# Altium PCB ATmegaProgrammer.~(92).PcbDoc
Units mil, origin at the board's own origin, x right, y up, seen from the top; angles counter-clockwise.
Board outline 2130 x 2720 mil, 2 copper layers (Top Layer, Bottom Layer); 14 components, 9 nets, 76 pads, 4 vias.
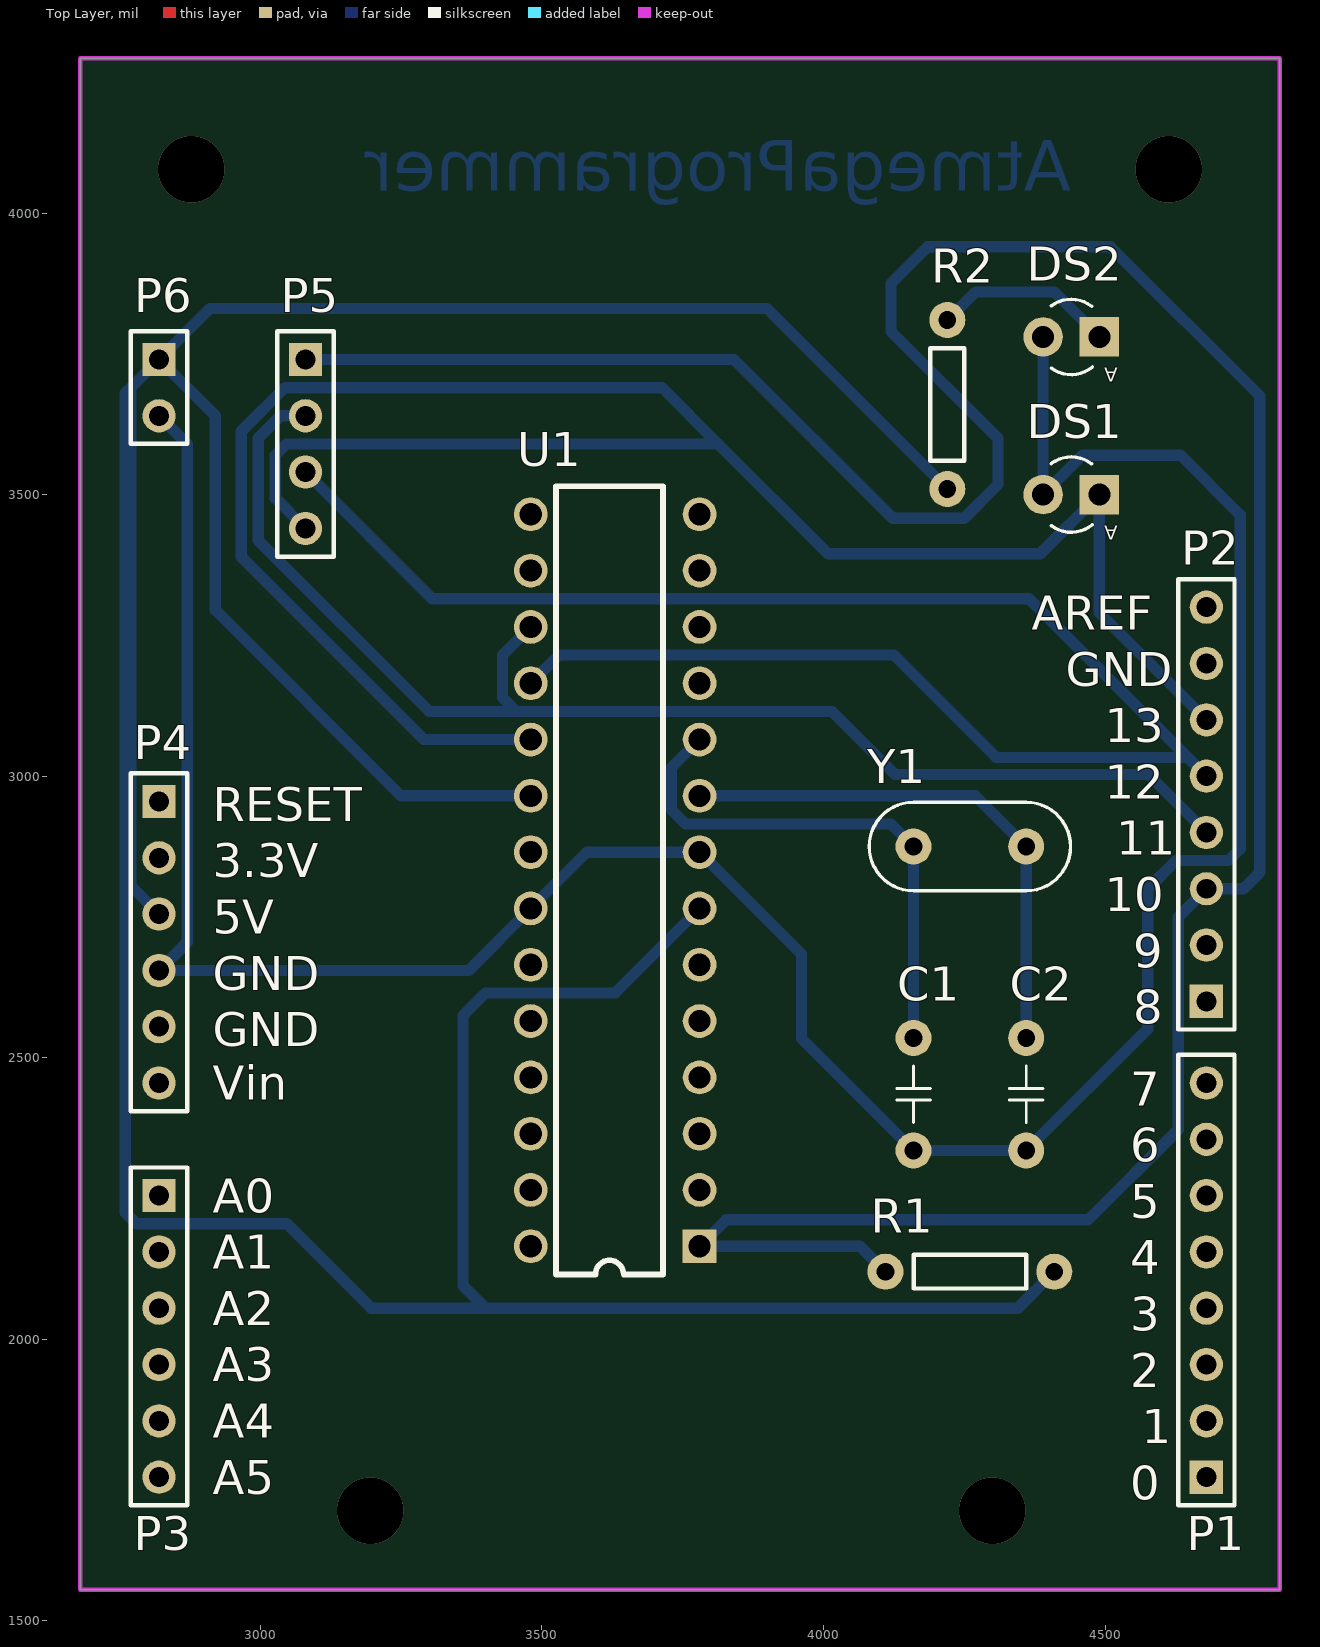
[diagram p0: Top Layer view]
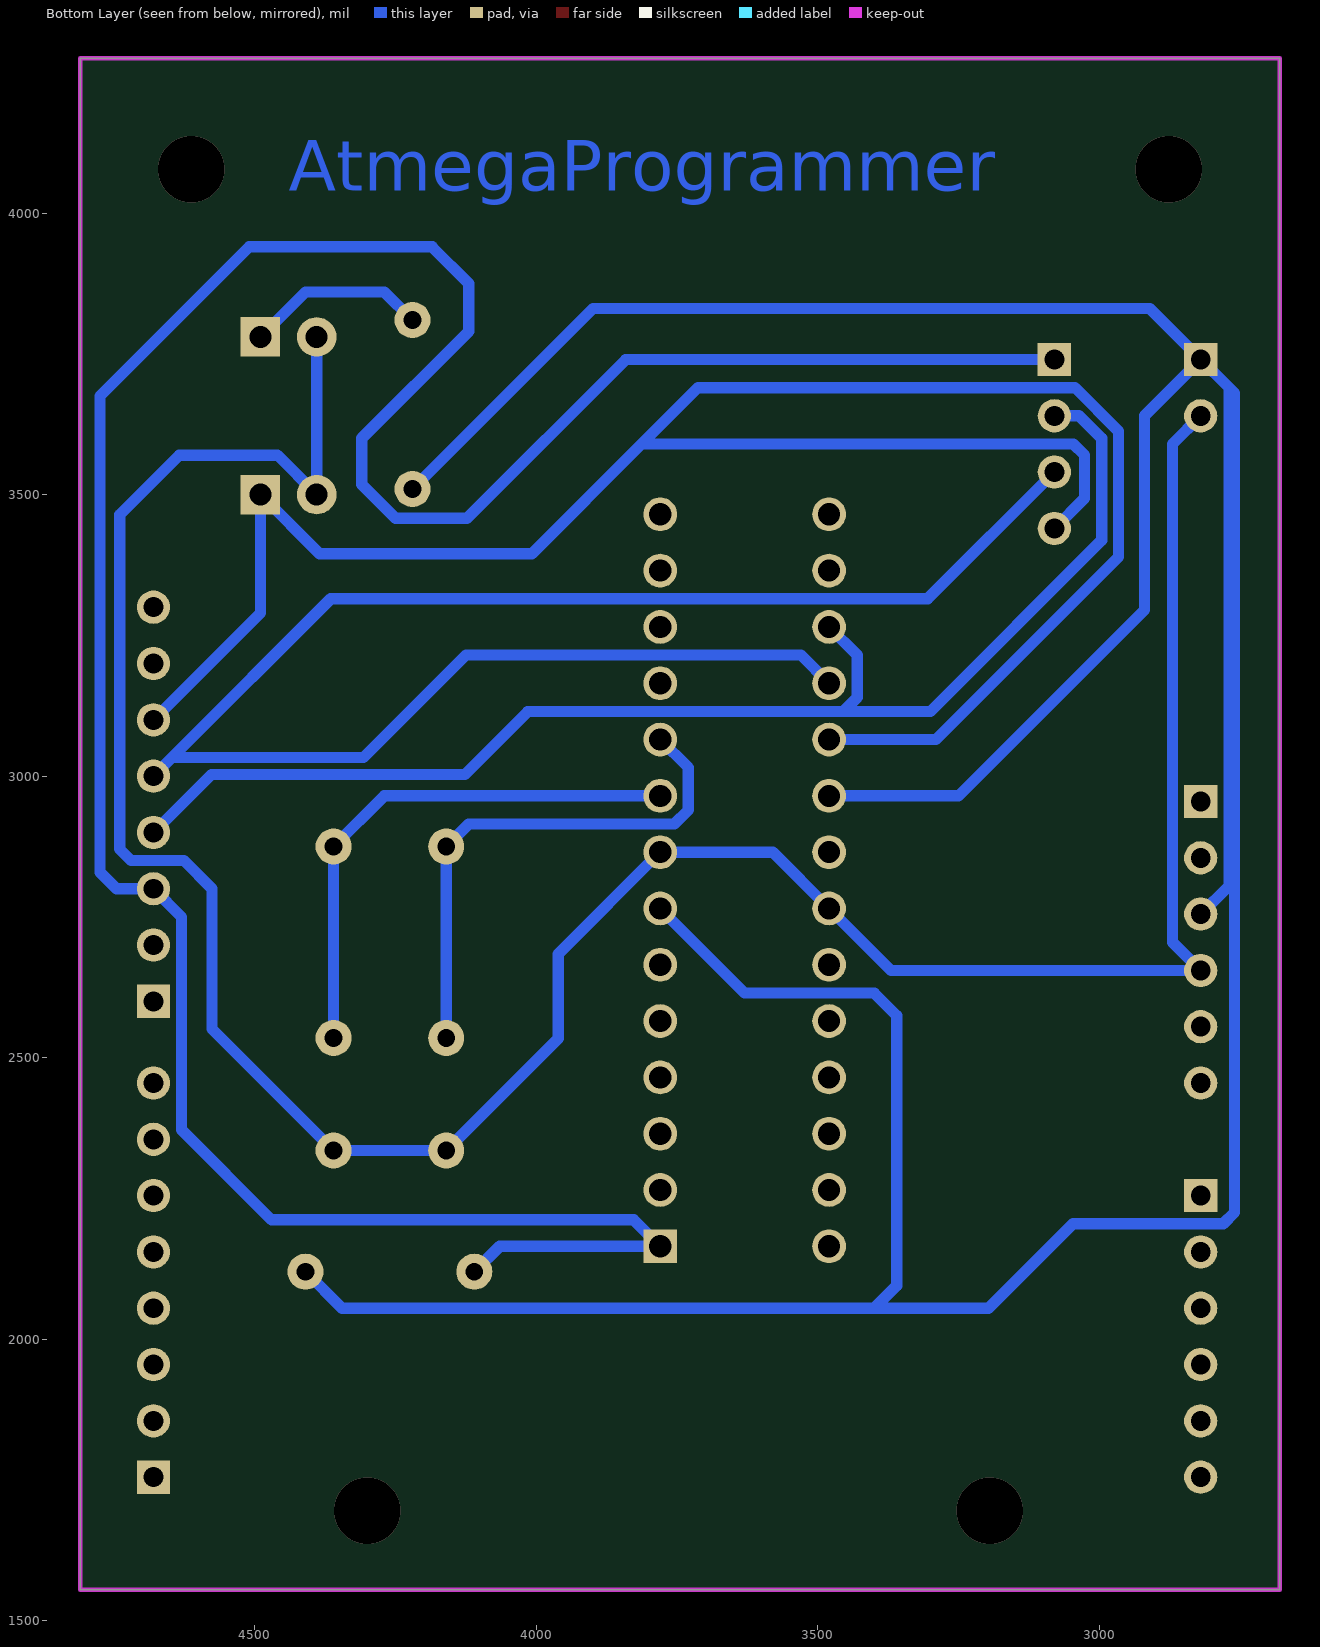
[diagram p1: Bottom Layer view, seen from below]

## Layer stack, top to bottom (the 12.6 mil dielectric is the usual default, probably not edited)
Top Layer: signal copper 1.4
Dielectric: dielectric 12.6, FR-4, Dk 4.8
Bottom Layer: signal copper 1.4

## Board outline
2680,1555 4810,1555 4810,4275 2680,4275

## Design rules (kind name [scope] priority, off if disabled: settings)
Clearance [All] p1: gap=10
PolygonConnect [All] p1: connectstyle=Relief reliefconductorwidth=10 reliefentries=4 polygonreliefangle="90 Angle"
RoutingLayers [All] p1: top layer_v5=FALSE bottom layer_v5=TRUE
RoutingVias [All] p1: holewidth=28 width=50 viastyle="Through Hole" minholewidth=28 minwidth=50 maxholewidth=28 maxwidth=50
SilkscreenOverComponentPads [All] p1: minsilkscreentomaskgap=10
SolderMaskExpansion [All] p1: expansion=4
Width [All] p1: maxlimit=40 minlimit=10 preferedwidth=20
26 further rules are at their usual default settings.

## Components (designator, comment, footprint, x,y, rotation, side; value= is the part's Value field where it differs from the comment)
C1 "20pF" C200 4160,2435 r180 top
C2 "20pF" C200 4360,2435 r180 top
DS1 "LED" LED-3mm_G 4440,3500 r180 top
DS2 "LED" LED-3mm_G 4440,3780 r180 top
P1 "Header 8" HDR1X8 4680,1755 r90 top
P2 "Header 8" HDR1X8 4680,2600 r90 top
P3 "Header 6" HDR1X6 2820,2255 r270 top
P4 "Header 6" HDR1X6 2820,2955 r270 top
P5 "Header 4" HDR1X4 3080,3740 r270 top
P6 "Header 2" HDR1X2 2820,3740 r270 top
R1 "10k" AXIAL-0.3 4260,2120 r0 top
R2 "220" AXIAL-0.3 4220,3660 r270 top
U1 "ATmega328" DIP28 3620,2820 r180 top
Y1 "16MHz" XTAL4-8 4260,2875 r180 top

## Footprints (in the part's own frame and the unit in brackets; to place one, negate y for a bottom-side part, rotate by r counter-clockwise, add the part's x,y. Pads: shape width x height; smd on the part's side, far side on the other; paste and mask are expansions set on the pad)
AXIAL-0.3 [mil] "0.3\" Resistor; 2 Leads"
  round 64 hole 31.5: 1(-150,0) 2(150,0)
  silkscreen extent -100,-30 100,30, body extent -161,-39 165,39, height 86
C200 [mil] "鹅溅筿甧竟"
  round 64 hole 31.5: 1(0,100) 2(0,-100)
  silkscreen extent -30,-50 30,50, body extent -41,-136 39,135, height 354
DIP28 [mil]
  rect 60x60 hole 39.37: 1(-160,655)
  round 60 hole 39.37: 2(-160,555) 3(-160,455) 4(-160,355) 5(-160,255) 6(-160,155) 7(-160,55) 8(-160,-45) 9(-160,-145) 10(-160,-245) 11(-160,-345) 12(-160,-445) 13(-160,-545) 14(-160,-645) 15(140,-645) 16(140,-545) 17(140,-445) 18(140,-345) 19(140,-245) 20(140,-145) 21(140,-45) 22(140,55) 23(140,155) 24(140,255) 25(140,355) 26(140,455) 27(140,555) 28(140,655)
  silkscreen extent -95,-695 95,705, body extent -95,-695 95,705, height 130
HDR1X2 [mm] "Connector; Header; 2 Position"
  rect 1.5x1.5 hole 0.9: 1(0,0)
  round 1.5 hole 0.9: 2(2.54,0)
  silkscreen extent -1.27,-1.27 3.81,1.27
HDR1X4 [mm] "Connector; Header; 4 Position"
  rect 1.5x1.5 hole 0.9: 1(0,0)
  round 1.5 hole 0.9: 2(2.54,0) 3(5.08,0) 4(7.62,0)
  silkscreen extent -1.27,-1.27 8.89,1.27
HDR1X6 [mm] "Connector; Header; 6 Position"
  rect 1.5x1.5 hole 0.9: 1(0,0)
  round 1.5 hole 0.9: 2(2.54,0) 3(5.08,0) 4(7.62,0) 5(10.16,0) 6(12.7,0)
  silkscreen extent -1.27,-1.27 13.97,1.27
HDR1X8 [mm] "Connector; Header; 8 Position"
  rect 1.5x1.5 hole 0.9: 1(0,0)
  round 1.5 hole 0.9: 2(2.54,0) 3(5.08,0) 4(7.62,0) 5(10.16,0) 6(12.7,0) 7(15.24,0) 8(17.78,0)
  silkscreen extent -1.27,-1.27 19.05,1.27
LED-3mm_G [mil] "3mm LED_Green"
  rect 70x70 hole 39: 1(-50,0)
  round 70 hole 39: 2(50,0)
  silkscreen extent -38,-67 35,67, body extent -66,-68 67,66, height 181
XTAL4-8 [mil]
  round 64 hole 31.5: 1(-100,0) 2(100,0)
  silkscreen extent -179,-79 179,79, body extent -178,-80 192,79, height 157

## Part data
C1 C2: library part Cap, "Capacitor"
DS1 DS2: "Typical INFRARED GaAs LED"
P1 P2: "Header, 8-Pin"
P3 P4: "Header, 6-Pin"
P5: "Header, 4-Pin"
P6: "Header, 2-Pin"
R1 R2: library part Res, "Resistor"
U1: "ATmega¨t¦C³æ´¹¤ù"
Y1: library part XTAL, "Crystal Oscillator"

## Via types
v1: diameter 118.11, hole 118.11, Top Layer to Bottom Layer, 4 vias

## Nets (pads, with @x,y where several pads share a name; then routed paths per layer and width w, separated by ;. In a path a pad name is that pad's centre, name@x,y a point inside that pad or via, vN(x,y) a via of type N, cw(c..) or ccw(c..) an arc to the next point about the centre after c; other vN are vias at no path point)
GND: C1.1 C2.1 DS1.2 DS2.2 P4.4 P6.2 U1.8 U1.22 | length 5004.9
  Bottom Layer w20: P6.2 2870,3590 2870,2705 P4.4 3370,2655 U1.22 3580,2865 U1.8 3961,2684 3961,2534 C1.1 C2.1 4576,2551 4576,2800 4626,2850 4719.53,2850 4740,2870.47 4740,3464 4634,3570 4460,3570 DS1.2 DS2.2
MISO: P2.5 P5.3 U1.18 | length 3133.4
  Bottom Layer w20: P5.3 3305,3315 4365,3315 4647,3033 ; U1.18 3530,3215 4125,3215 4307,3033 4647,3033 ; 4647,3033 P2.5 4647,3033
MOSI: P2.4 P5.2 U1.17 | length 2921.6
  Bottom Layer w20: P5.2 3036,3640 2996,3600 2996,3419 3300,3115 3455,3115 ; U1.17 3430,3215 3430,3140 3455,3115 ; P2.4 4577,3003 4127,3003 4015,3115 ; 3455,3115 4015,3115 ; 3455,3115 4015,3115
NetC1_2: C1.2 U1.10 Y1.2 | length 942.6
  Bottom Layer w20: U1.10 3730,3015 3730,2940 3755,2915 4120,2915 Y1.2 C1.2
NetC2_2: C2.2 U1.9 Y1.1 | length 957.3
  Bottom Layer w20: U1.9 4270,2965 Y1.1 C2.2
NetDS2_1: DS2.1 R2.1 | length 323.8
  Bottom Layer w20: R2.1 4270,3860 4410,3860 DS2.1
RESET: P2.3 P5.1 R1.1 U1.1 | length 5285
  Bottom Layer w20: P5.1 3841,3740 4123,3458 4250,3458 4310,3518 4310,3600 4120,3790 4120,3875 4185,3940 4510,3940 4775,3675 4775,2829.29 4745.71,2800 P2.3 4630,2750 4630,2372 4470,2212 3827,2212 U1.1 4065,2165 R1.1
SCK: DS1.1 P2.6 P5.4 U1.19 | length 4294.9
  Bottom Layer w20: P5.4 3026.45,3493.55 3026.45,3570 3046.45,3590 3813,3590 ; U1.19 3290,3065 2966,3389 2966,3612.43 3043.57,3690 3713,3690 3813,3590 ; P2.6 4490,3290 DS1.1 4385,3395 4008,3395 ; 3813,3590 4008,3395 ; 3813,3590 4008,3395
VCC: P4.3 P6.1 R1.2 R2.2 U1.7 U1.20 | length 9047.2
  Bottom Layer w20: P4.3 2770,2805 2770,3690 ; U1.20 3250,2965 2920,3295 2920,3640 P6.1 ; U1.7 3630,2615 3400,2615 3360,2575 3360,2095 3400,2055 ; R2.2 3899.49,3830.51 2910.51,3830.51 P6.1 ; R1.2 4345,2055 ; 2770,3690 P6.1 ; 2770,3690 2760,3680 2760,2225 2780,2205 3047,2205 3197,2055 3400,2055 ; 2770,3690 P6.1 ; 3400,2055 4345,2055 ; 3400,2055 4345,2055
pads on no net: P1.1 P1.2 P1.3 P1.4 P1.5 P1.6 P1.7 P1.8 P2.1 P2.2 P2.7 P2.8 P3.1 P3.2 P3.3 P3.4 P3.5 P3.6 P4.1 P4.2 P4.5 P4.6 U1.2 U1.3 U1.4 U1.5 U1.6 U1.11 U1.12 U1.13 U1.14 U1.15 U1.16 U1.21 U1.23 U1.24 U1.25 U1.26 U1.27 U1.28
copper on no net:
  other v1: 3195,1695 4300,1695 2876.85,4078.15 4613.15,4078.15

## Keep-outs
Keep-Out Layer:
  the board outline again, w7.87

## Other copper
Bottom Layer:
  text "AtmegaProgrammer" at 4440,4040 h90

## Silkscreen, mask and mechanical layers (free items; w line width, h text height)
Top Overlay:
  lines w7.87: 0,0 0,200 ; 20,0 35,0 ; 55,0 195,0 ; 2770,2246.75 2770,2255
  text "AREF" at 4370,3260 h60
  text "GND" at 4429.98,3160 h60
  text "13" at 4499.96,3060 h60
  text "12" at 4499.96,2960 h60
  text "RESET" at 2915.05,2920 h60
  text "11" at 4519.95,2860 h60
  text "3.3V" at 2915.05,2820 h60
  text "10" at 4499.96,2760 h60
  text "5V" at 2915.05,2720 h60
  text "9" at 4549.94,2660 h60
  text "GND" at 2915.05,2620 h60
  text "8" at 4549.94,2560 h60
  text "GND" at 2915.05,2520 h60
  text "Vin" at 2915.05,2425 h60
  text "7" at 4544.94,2415 h60
  text "6" at 4544.94,2315 h60
  text "A0" at 2915.05,2225 h60
  text "5" at 4544.94,2215 h60
  text "A1" at 2915.05,2125 h60
  text "4" at 4544.94,2115 h60
  text "A2" at 2915.05,2025 h60
  text "3" at 4544.94,2015 h60
  text "A3" at 2915.05,1925 h60
  text "2" at 4544.94,1915 h60
  text "A4" at 2915.05,1825 h60
  text "1" at 4564.94,1815 h60
  text "A5" at 2915.05,1725 h60
  text "0" at 4544.94,1715 h60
